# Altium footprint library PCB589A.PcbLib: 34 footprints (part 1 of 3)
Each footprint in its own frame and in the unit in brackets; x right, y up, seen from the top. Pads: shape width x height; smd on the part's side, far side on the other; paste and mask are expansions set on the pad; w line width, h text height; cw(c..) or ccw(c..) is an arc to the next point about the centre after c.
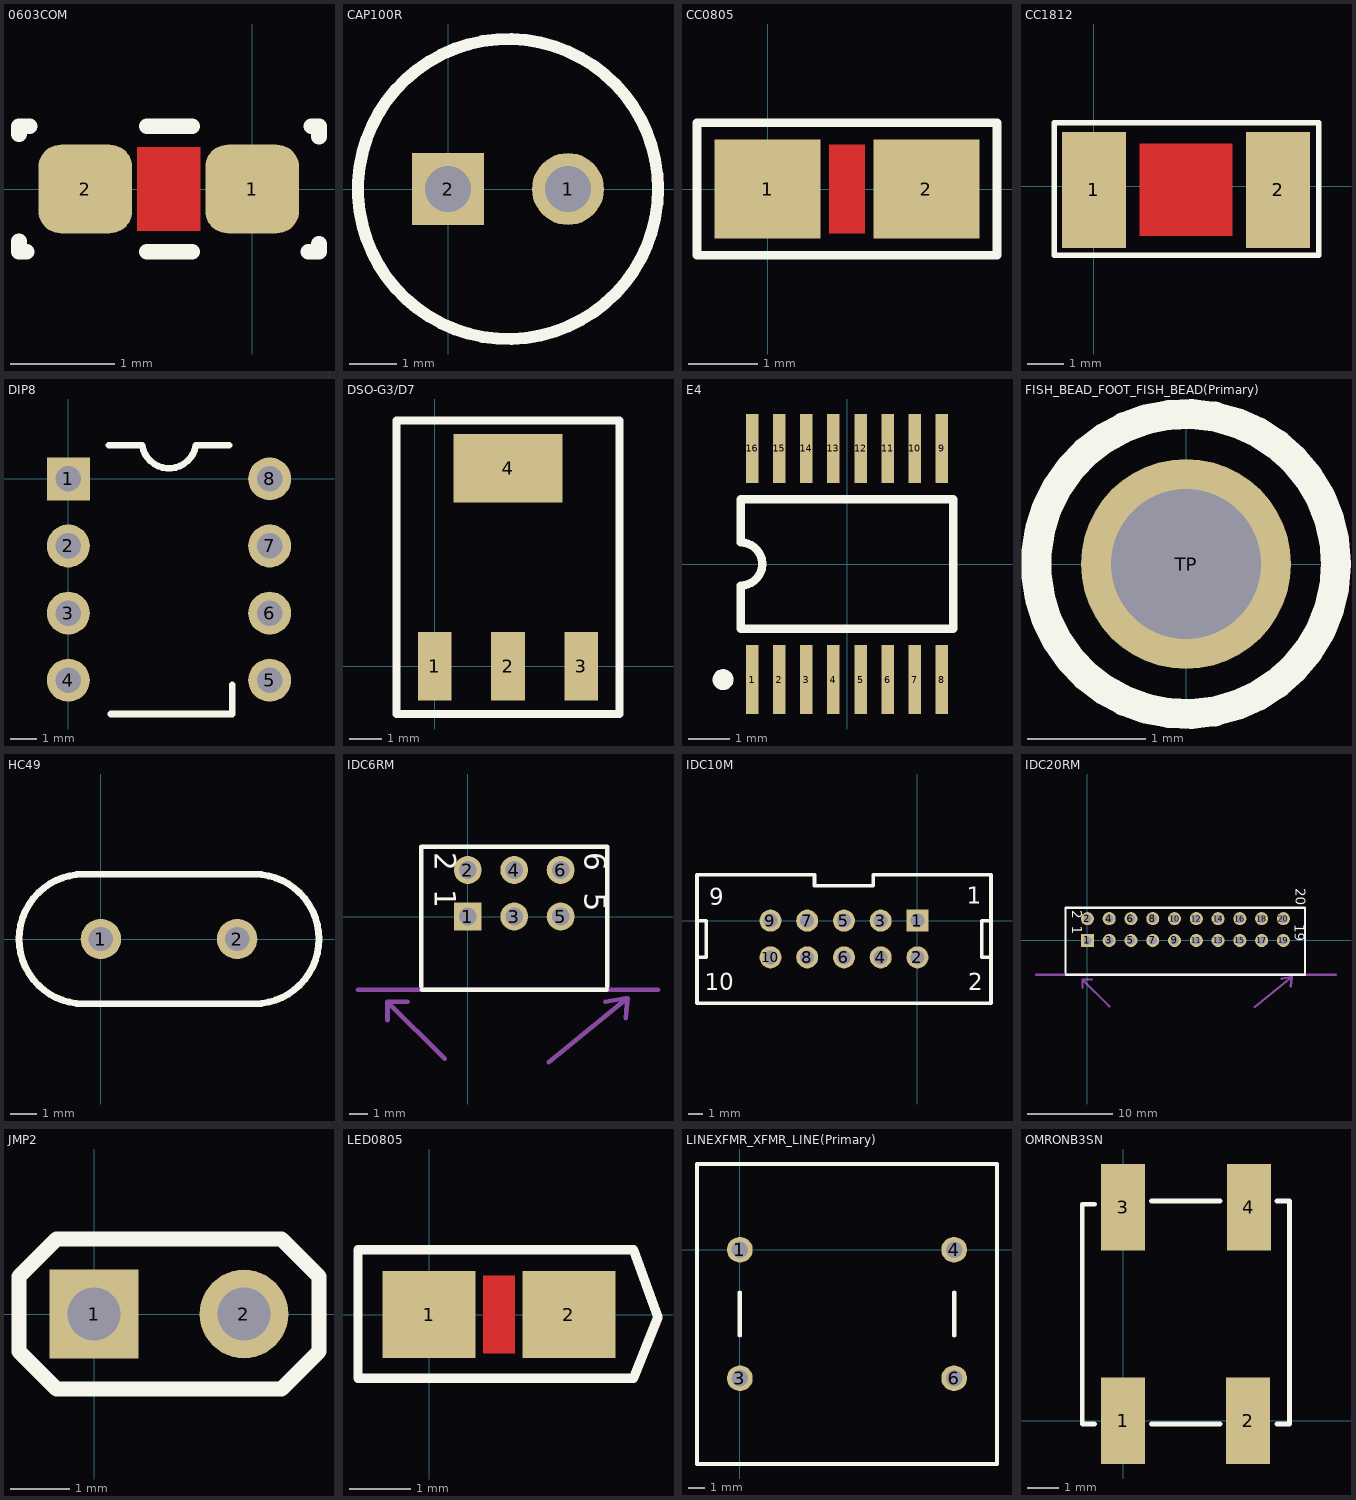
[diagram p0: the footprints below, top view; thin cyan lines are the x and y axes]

## 0603COM [mm]
pads (2):
  rrect50% 0.9x0.85 smd: 1(0,0) 2(-1.6,0)
Top Layer:
  region: -1.1,-0.4 -0.5,-0.4 -0.5,0.4 -1.1,0.4
Top Overlay:
  lines w0.15: -2.235,-0.5 -2.235,-0.6 -2.16,-0.6 ; -2.235,0.525 -2.235,0.6 -2.135,0.6 ; -1.01,-0.6 -0.575,-0.6 ; -1.01,0.6 -0.575,0.6 ; 0.54,-0.6 0.64,-0.6 0.64,-0.525 ; 0.565,0.6 0.64,0.6 0.64,0.5

## CAP100R [mil]
pads (2):
  round 60 hole 38: 1(100,0)
  rect 60x60 hole 38: 2(0,0)
Top Overlay:
  circle w10: c50,0 r125

## CC0805 [mil]
pads (2):
  rect 60x56 smd: 1(0,0) 2(90,0)
Top Layer:
  region: 55,-25 55,25 35,25 35,-25
Top Overlay:
  lines w5: -40,-37.5 130,-37.5 130,37.5 -40,37.5 -40,-37.5

## CC1812 [mil]
pads (2):
  rect 70x126 smd: 1(0,-3.94) 2(200,-3.94)
Top Layer:
  region: 150,-53.94 150,46.06 50,46.06 50,-53.94
Top Overlay:
  lines w5.98: -43.31,-74.8 244.09,-74.8 244.09,68.9 -43.31,68.9 -43.31,-74.8

## DIP8 [mil]
pads (8):
  rect 64x64 hole 38: 1(0,0)
  round 64 hole 38: 2(0,-100) 3(0,-200) 4(0,-300) 5(300,-300) 6(300,-200) 7(300,-100) 8(300,0)
Top Overlay:
  lines w10: 60,50 110,50 ccw(c150,56.23) 190,50 240,50 ; 62.99,-350.39 244.09,-350.39 244.09,-307.09

## DSO-G3/D7 [mm]
pads (4):
  rect 1.05x2.15 smd: 1(0,0) 2(2.3,0) 3(4.6,0)
  rect 3.4x2.15 smd: 4(2.3,6.2)
Top Overlay:
  lines w0.25: -1.2,-1.5 5.8,-1.5 5.8,7.7 -1.2,7.7 -1.2,-1.5

## E4 [mm]
pads (16):
  rect 0.3x1.65 smd: 1(-2.275,-2.775) 2(-1.625,-2.775) 3(-0.975,-2.775) 4(-0.325,-2.775) 5(0.325,-2.775) 6(0.975,-2.775) 7(1.625,-2.775) 8(2.275,-2.775) 9(2.275,2.775) 10(1.625,2.775) 11(0.975,2.775) 12(0.325,2.775) 13(-0.325,2.775) 14(-0.975,2.775) 15(-1.625,2.775) 16(-2.275,2.775)
Top Overlay:
  circle w0.25: c-2.975,-2.775 r0.125
  lines w0.2: -2.55,-1.55 2.55,-1.55 2.55,1.55 -2.55,1.55 -2.55,0.517 cw(c-2.55,0) -2.55,-0.517 -2.55,-1.55

## FISH_BEAD_FOOT_FISH_BEAD(Primary) [mil]
pads (1):
  round 70 hole 50: TP(0,0)
Top Overlay:
  circle w10: c0,0 r50

## HC49 [mm]
pads (2):
  round 1.5 hole 0.9: 1(0,0) 2(5.08,0)
Top Overlay:
  lines w0.254: -0.635,-2.413 cw(c-0.635,0) -0.635,2.413 5.715,2.413 cw(c5.715,0) 5.715,-2.413 -0.635,-2.413

## IDC6RM [mil]
pads (6):
  rect 60x60 hole 38: 1(0,0)
  round 60 hole 38: 2(0,100) 3(100,0) 4(100,100) 5(200,0) 6(200,100)
Top Overlay:
  lines w10: -100,-150 -100,150 300,150 300,-150 ; -98.43,-157.48 299.21,-157.48
  text "2" at -86.61,137.8 h78.74
  text "1" at -86.61,59.06 h78.74
  text "5" at 236.22,51.18 h78.74
  text "6" at 236.22,137.8 h78.74
Mechanical 1:
  lines w10: -236.22,-157.48 409.45,-157.48 ; -172.83,-222.83 -172.83,-183.46 -49.61,-305.91 ; -168.9,-183.46 -129.53,-183.46 ; 174.41,-313.39 343.7,-175.59 339.76,-218.9 ; 296.46,-183.46 339.76,-175.59
  text "Edge of card" at 350.39,-350.39 h78.74

## IDC10M [mil]
pads (10):
  rect 60x60 hole 38: 1(0,0)
  round 60 hole 38: 2(0,-100) 3(-100,0) 4(-100,-100) 5(-200,0) 6(-200,-100) 7(-300,0) 8(-300,-100) 9(-400,0) 10(-400,-100)
Top Overlay:
  lines w10: -600,-100 -575,-100 -575,0 -600,0 ; 200,-100 175,-100 175,0 200,0 ; -600,-225 200,-225 200,125 -120,125 -120,95 -280,95 -280,125 -600,125 -600,-225
  text "2" at 137.8,-204.72 h78.74
  text "1" at 133.86,31.5 h78.74
  text "10" at -578.74,-204.72 h78.74
  text "9" at -566.93,27.56 h78.74

## IDC20RM [mil]
pads (20):
  rect 60x60 hole 38: 1(0,0)
  round 60 hole 38: 2(0,100) 3(100,0) 4(100,100) 5(200,0) 6(200,100) 7(300,0) 8(300,100) 9(400,0) 10(400,100) 11(500,0) 12(500,100) 13(600,0) 14(600,100) 15(700,0) 16(700,100) 17(800,0) 18(800,100) 19(900,0) 20(900,100)
Top Overlay:
  lines w10: -100,-150 -100,150 1000,150 1000,-150 ; -98.43,-157.48 1000,-157.48
  text "20" at 940.94,240.16 h78.74
  text "19" at 937.01,74.8 h78.74
  text "1" at -86.61,66.93 h78.74
  text "2" at -86.61,137.8 h78.74
Mechanical 1:
  lines w10: -236.22,-157.48 1141.73,-157.48 ; -23.23,-218.9 -23.23,-179.53 100,-301.97 ; -19.29,-179.53 20.08,-179.53 ; 768.9,-305.51 938.19,-167.72 934.25,-211.02 ; 890.94,-175.59 934.25,-167.72
  text "Edge of card" at 700,-300 h98.43

## JMP2 [mm]
pads (2):
  rect 1.5x1.5 hole 0.9: 1(0,0)
  round 1.5 hole 0.9: 2(2.54,0)
Top Overlay:
  lines w0.254: -1.27,-0.635 -1.27,0.635 -0.635,1.27 3.175,1.27 3.81,0.635 3.81,-0.635 3.175,-1.27 -0.635,-1.27 -1.27,-0.635

## LED0805 [mil]
pads (2):
  rect 60x56 smd: 1(0,0) 2(90,0)
Top Layer:
  region: 55,-25 55,25 35,25 35,-25
Top Overlay:
  lines w5.91: -45.67,-40.94 131.5,-40.94 147.24,-1.57 131.5,41.73 -45.67,41.73 -45.67,-40.94

## LINEXFMR_XFMR_LINE(Primary) [mil]
pads (4):
  round 60 hole 38: 1(0,0) 3(0,-300) 4(500,0) 6(500,-300)
Top Overlay:
  lines w10: 0,-200 0,-100 ; 500,-200 500,-100 ; -100,-500 -100,200 600,200 600,-500 -100,-500

## OMRONB3SN [mm]
pads (4):
  rect 1.4x2.75 smd: 1(0,0) 2(3.988,0) 3(0,6.807) 4(4.013,6.807)
Top Overlay:
  lines w0.152: -0.9,-0.1 -1.3,-0.1 -1.3,6.9 -0.9,6.9 ; 0.9,-0.1 3.1,-0.1 ; 0.9,7 3.1,7 ; 4.9,-0.1 5.3,-0.1 5.3,7 4.9,7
